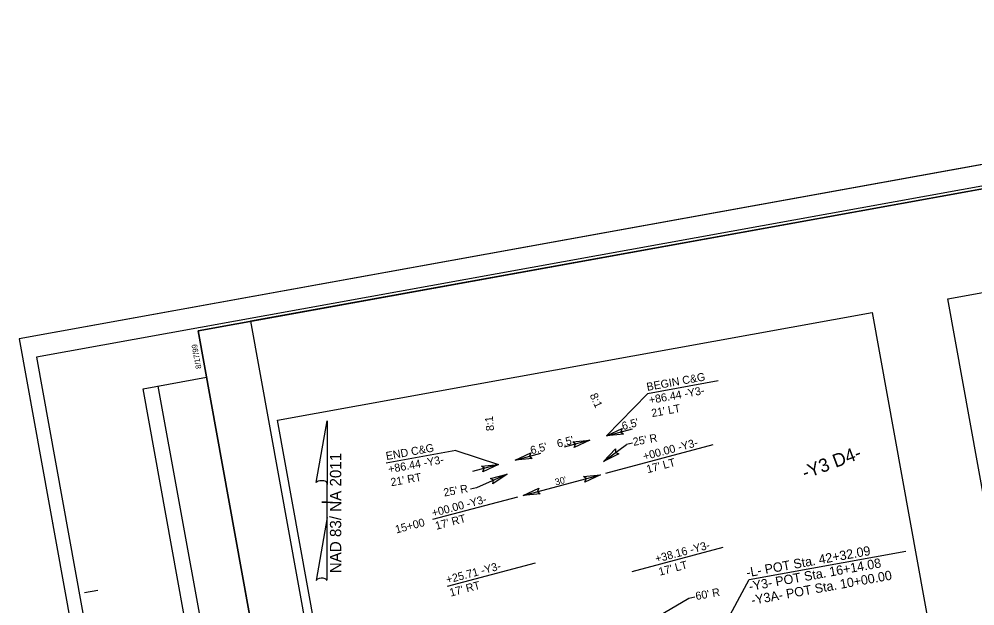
# Model space of a CAD drawing. Extents: x 1620721 to 1621526, y 897852 to 898403.
# Drawn here: x 1620721.2 to 1621079.6, y 898182.7 to 898402.8 of the extents above; entities that cross this region are included whole.
import ezdxf

# ---------------------------------------------------------------- set-up
doc = ezdxf.new("R2010")
doc.units = 0
for name, color, linetype in [('Prop Conc 2ft 6in Curb and Gutter', 7, 'Continuous'), ('Prop Dimension', 7, 'Continuous'), ('Prop DSN Text', 7, 'Continuous'), ('Prop Horizontal Alignment Direction Label', 7, 'Continuous'), ('Prop Horizontal Alignment Station Label', 7, 'Continuous'), ('Prop North Arrow NAD83 for Plan Sheets CELL', 7, 'Continuous'), ('Prop Terminator CELL', 7, 'Continuous'), ('Sheet Block Revision CELL', 7, 'Continuous'), ('Sheet Clip Boundary CELL', 7, 'Continuous'), ('Sheet Cutting Line CELL', 7, 'Continuous'), ('Sheet Layout Plan Border', 7, 'Continuous'), ('Sheet Plan CELL', 7, 'Continuous'), ('Sheet Plot Border Inside CELL', 7, 'Continuous'), ('Sheet Plot Border Outside CELL', 7, 'Continuous')]:
    doc.layers.add(name, color=color, linetype=linetype)

msp = doc.modelspace()

# ---------------------------------------------------------------- linework, layer by layer
at = {"layer": 'Prop Conc 2ft 6in Curb and Gutter'}
for p, q in [((1620983.28, 898267.05), (1620956.86, 898262.26)), ((1620956.86, 898262.26), (1620941.51, 898246.48)), ((1620884.92, 898240.97), (1620858.88, 898236.26)), ((1620884.92, 898240.97), (1620900.91, 898235.7)), ((1620981.36, 898243.03), (1620941.12, 898232.34)), ((1620876.38, 898215.15), (1620908.26, 898223.61)), ((1620985.1, 898204.53), (1620950.92, 898195.46)), ((1620881.82, 898190), (1620914.86, 898198.77))]:
    msp.add_line(p, q, dxfattribs=at)
at = {"layer": 'Prop Dimension'}
for p, q in [((1620941.51, 898246.48), (1620951.17, 898249.04)), ((1620935.21, 898244.81), (1620925.55, 898242.24)), ((1620940.36, 898236.86), (1620948.98, 898243.25)), ((1620951.26, 898243.67), (1620948.98, 898243.25)), ((1620907.2, 898237.37), (1620916.87, 898239.93)), ((1620900.91, 898235.7), (1620891.25, 898233.13)), ((1620904.17, 898232.1), (1620892.7, 898226.9)), ((1620910.19, 898224.13), (1620939.19, 898231.83)), ((1620892.7, 898226.9), (1620890.42, 898226.49)), ((1620972.27, 898185.47), (1620959, 898177.55)), ((1620974.55, 898185.89), (1620972.27, 898185.47))]:
    msp.add_line(p, q, dxfattribs=at)
at = {"layer": 'Prop DSN Text'}
for points in [[(1621069.41, 898297.84), (1621292.41, 898338.21), (1621348.65, 898027.48), (1621125.66, 897987.11)], [(1620818.11, 898252.36), (1621041.11, 898292.72), (1621097.35, 897981.99), (1620874.36, 897941.62)]]:
    msp.add_lwpolyline(points, close=True, dxfattribs=at)
at = {"layer": 'Prop Horizontal Alignment Station Label'}
for p, q in [((1620994.9, 898192.6), (1621053.66, 898203.24)), ((1620954.2, 898116.85), (1620994.9, 898192.6))]:
    msp.add_line(p, q, dxfattribs=at)
at = {"layer": 'Prop North Arrow NAD83 for Plan Sheets CELL'}
for p, q in [((1620832.61, 898228.91), (1620836.72, 898252.08)), ((1620836.74, 898252.08), (1620836.72, 898252.08)), ((1620836.74, 898252.08), (1620836.72, 898252.08)), ((1620836.74, 898252.08), (1620836.73, 898228.18)), ((1620836.73, 898215.78), (1620836.73, 898228.88)), ((1620836.73, 898228.18), (1620836.73, 898228.86)), ((1620834.73, 898221.58), (1620834.71, 898221.58)), ((1620836.51, 898221.58), (1620834.73, 898221.58)), ((1620834.76, 898221.58), (1620838.76, 898221.58)), ((1620836.73, 898215.78), (1620832.55, 898192.16)), ((1620836.75, 898192.26), (1620836.73, 898215.78))]:
    msp.add_line(p, q, dxfattribs=at)
for centre, start_param, end_param in [((1620834.68, 898228.66), 0.216388, 2.908219), ((1620834.66, 898192.07), 0.201328, 3.141593)]:
    msp.add_ellipse(centre, major_axis=(2.11, -0.02), ratio=0.461098, start_param=start_param, end_param=end_param, dxfattribs=at)
at = {"layer": 'Prop Terminator CELL'}
for points in [[(1620947.87, 898247.05), (1620941.51, 898246.48), (1620947.34, 898249.19), (1620946.85, 898247.9)], [(1620928.85, 898244.24), (1620935.21, 898244.81), (1620929.38, 898242.1), (1620929.87, 898243.39)], [(1620946.06, 898239.74), (1620940.36, 898236.86), (1620944.78, 898241.53), (1620944.8, 898240.15)], [(1620913.57, 898237.94), (1620907.2, 898237.37), (1620913.04, 898240.08), (1620912.55, 898238.79)], [(1620894.55, 898235.13), (1620900.91, 898235.7), (1620895.08, 898232.99), (1620895.57, 898234.28)], [(1620897.98, 898230.49), (1620904.17, 898232.1), (1620898.86, 898228.47), (1620899.13, 898229.82)], [(1620932.82, 898231.26), (1620939.19, 898231.83), (1620933.35, 898229.12), (1620933.84, 898230.41)], [(1620916.56, 898224.7), (1620910.19, 898224.13), (1620916.03, 898226.84), (1620915.54, 898225.55)]]:
    msp.add_lwpolyline(points, close=True, dxfattribs=at)
at = {"layer": 'Sheet Block Revision CELL'}
msp.add_line((1620829.72, 897953.94), (1620773.38, 898265.13), dxfattribs=at)
msp.add_lwpolyline([(1620823.99, 897952.89), (1620767.66, 898264.09), (1620791.49, 898268.42), (1620847.82, 897957.21)], close=True, dxfattribs=at)
at = {"layer": 'Sheet Clip Boundary CELL'}
msp.add_lwpolyline([(1620882.81, 897876.15), (1621433.86, 897975.9), (1621374.12, 898305.94), (1621299.62, 898292.45), (1621284.56, 898375.7), (1620808, 898289.43)], close=True, dxfattribs=at)
at = {"layer": 'Sheet Cutting Line CELL'}
for p, q in [((1621383.82, 898402.8), (1620721.19, 898282.86)), ((1620721.19, 898282.86), (1620799.2, 897851.87))]:
    msp.add_line(p, q, dxfattribs=at)
at = {"layer": 'Sheet Layout Plan Border'}
msp.add_lwpolyline([(1620882.81, 897876.15), (1621433.86, 897975.9), (1621374.12, 898305.94), (1621299.62, 898292.45), (1621284.56, 898375.7), (1620808, 898289.43)], close=True, dxfattribs=at)
at = {"layer": 'Sheet Plan CELL'}
for p, q in [((1620788.32, 898285.87), (1620788.32, 898285.87)), ((1620745.72, 898187.71), (1620750.65, 898188.61))]:
    msp.add_line(p, q, dxfattribs=at)
for points in [[(1621378.74, 898392.74), (1620788.32, 898285.87), (1620863.13, 897872.59), (1621453.54, 897979.46)], [(1620863.13, 897872.59), (1620788.31, 898285.86), (1621299.99, 898378.49), (1621310.69, 898319.43), (1621389.42, 898333.68), (1621453.54, 897979.46)]]:
    msp.add_lwpolyline(points, close=True, dxfattribs=at)
at = {"layer": 'Sheet Plot Border Inside CELL'}
msp.add_lwpolyline([(1620802.89, 897860.66), (1621458.63, 897979.36), (1621383.47, 898394.61), (1620727.73, 898275.92)], close=True, dxfattribs=at)
at = {"layer": 'Sheet Plot Border Outside CELL'}
msp.add_lwpolyline([(1620799.2, 897851.87), (1621461.84, 897971.81), (1621383.82, 898402.8), (1620721.19, 898282.86)], close=True, dxfattribs=at)

# ---------------------------------------------------------------- texts
at = {"layer": 'Prop Conc 2ft 6in Curb and Gutter'}
for s, rotation, p in [('BEGIN C&G', 10.2599, (1620956.76, 898263.31)), ('+86.44 -Y3-', 10.2599, (1620957.65, 898258.39)), ("21' LT", 10.2599, (1620958.54, 898253.47)), ('+00.00 -Y3-', 14.8727, (1620955.6, 898237.24)), ('END C&G', 10.2599, (1620858.99, 898237.37)), ('+86.44 -Y3-', 10.2599, (1620859.88, 898232.45)), ("17' LT", 14.8727, (1620956.88, 898232.41)), ("21' RT", 10.2599, (1620860.77, 898227.53)), ('+00.00 -Y3-', 14.8727, (1620876.38, 898216.01)), ("17' RT", 14.8727, (1620877.66, 898211.18)), ('+38.16 -Y3-', 14.8727, (1620960.13, 898198.8)), ('+25.71 -Y3-', 14.8727, (1620881.74, 898190.96)), ("17' LT", 14.8727, (1620961.42, 898193.96)), ("17' RT", 14.8727, (1620883.02, 898186.12))]:
    msp.add_text(s, height=3, rotation=rotation, dxfattribs=at).set_placement(p)
at = {"layer": 'Prop Dimension'}
for s, height, rotation, p in [('8:1', 3, 294.1075, (1620935.09, 898261.69)), ('8:1', 3, 95.6429, (1620899.34, 898248.42)), ("6.5'", 3, 14.8727, (1620947.62, 898248.58)), ("6.5'", 3, 14.8727, (1620923.28, 898241.97)), ("25' R", 3, 10.2599, (1620951.63, 898242.69)), ("6.5'", 3, 14.8727, (1620913.32, 898239.47)), ("30'", 2.5, 14.8727, (1620922.47, 898227.81)), ("25' R", 3, 10.2599, (1620880.62, 898223.67)), ("60' R", 3, 10.2599, (1620975.1, 898184.83))]:
    msp.add_text(s, height=height, rotation=rotation, dxfattribs=at).set_placement(p)
at = {"layer": 'Prop Horizontal Alignment Direction Label'}
msp.add_text('-Y3 D4-', height=5, rotation=20.5237, dxfattribs=at).set_placement((1621015.87, 898230.12))
at = {"layer": 'Prop Horizontal Alignment Station Label'}
for s, height, rotation, p in [('15+00', 3, 14.8727, (1620862.66, 898209.81)), ('-L- POT Sta. 42+32.09', 3.5, 10.2599, (1620994.21, 898193.37)), ('-Y3- POT Sta. 16+14.08', 3.5, 10.2599, (1620995.14, 898188.2)), ('-Y3A- POT Sta. 10+00.00', 3.5, 10.2599, (1620996.08, 898183.04))]:
    msp.add_text(s, height=height, rotation=rotation, dxfattribs=at).set_placement(p)
at = {"layer": 'Prop North Arrow NAD83 for Plan Sheets CELL'}
msp.add_text('NAD 83/ NA 2011', height=4.25, rotation=89.9808, dxfattribs=at).set_placement((1620841.98, 898194.9))
at = {"layer": 'Sheet Plan CELL'}
msp.add_text('8/17/99', height=2.1, rotation=100.26, dxfattribs=at).set_placement((1620789.56, 898271.78))

doc.saveas('drawing.dxf')
